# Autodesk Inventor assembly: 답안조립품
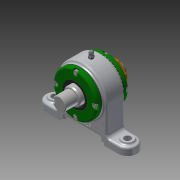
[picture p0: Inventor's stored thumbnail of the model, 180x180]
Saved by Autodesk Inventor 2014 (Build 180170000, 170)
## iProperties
Created: 2019-05
Part Number: 답안조립품
Document SubType Name: Assembly
Designer: kh
Author: kh
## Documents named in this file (13)
- C:\Users\kh\Desktop\490504V1009\답안조립품.iam
- C:\Users\kh\Desktop\490504V1009\본체.ipt
- C:\Users\kh\Desktop\490504V1009\개스킷.ipt
- C:\Users\kh\Desktop\490504V1009\그리스니플 M6.ipt
- 그리스니플  M6.ipt
- C:\Users\kh\Desktop\490504V1009\그리스니플개스킷.ipt
- C:\Users\kh\Desktop\490504V1009\베어링너트.ipt
- C:\Users\kh\Desktop\490504V1009\볼트 M4.ipt
- C:\Users\kh\Desktop\490504V1009\앵귤러 볼 베어링 7205.ipt
- C:\Users\kh\Desktop\490504V1009\오일 실 28 40 5 B.ipt
- C:\Users\kh\Desktop\490504V1009\축.ipt
- C:\Users\kh\Desktop\490504V1009\칼라.ipt
- C:\Users\kh\Desktop\490504V1009\커버.ipt
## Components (4 placed, 3 different names)
1. 개스킷:1 — Insert:10, Mate:2, Mate:4
2. 그리스니플  M6:1 — Insert:11, Angle:1
3. 그리스니플개스킷:1 — Insert:11, Insert:12
4. 개스킷:2 — Insert:9, Mate:1, Insert:13, Mate:3
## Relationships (10: Insert 5, Mate 4, Angle 1)
- Insert:9: 개스킷:2
- Mate:1: 개스킷:2
- Insert:10: 개스킷:1
- Mate:2: 개스킷:1
- Insert:11: 그리스니플  M6:1 ↔ 그리스니플개스킷:1
- Insert:12: 그리스니플개스킷:1
- Angle:1: 그리스니플  M6:1
- Insert:13: 개스킷:2
- Mate:3: 개스킷:2
- Mate:4: 개스킷:1
